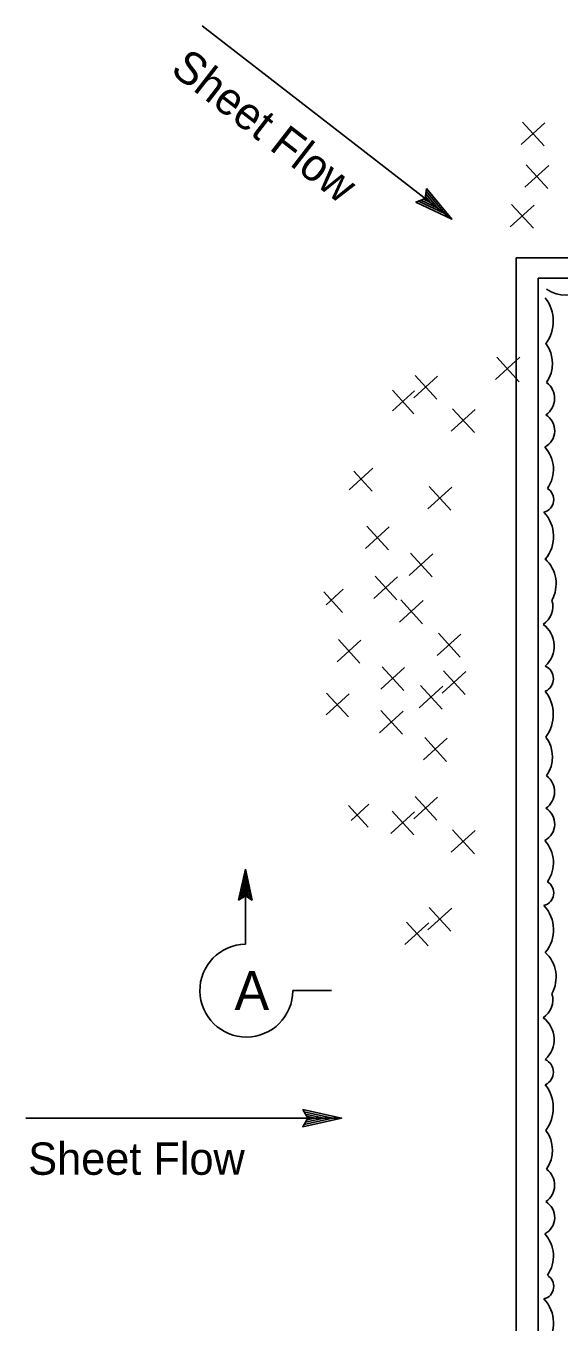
# Model space of a CAD drawing. Extents: x 6708945 to 6710368, y 1871409 to 1872338.
# Drawn here: x 6708945.2 to 6709044.1, y 1871623 to 1871863.4 of the extents above; entities that cross this region are included whole.
import ezdxf

# ---------------------------------------------------------------- set-up
doc = ezdxf.new("R2010")
doc.units = 0
for name, color, linetype in [('1 Control', 7, 'Continuous'), ('57 Undefined', 7, 'Continuous'), ('62 As-Built Chng', 7, 'Continuous'), ('63 Undefined', 7, 'Continuous')]:
    doc.layers.add(name, color=color, linetype=linetype)

msp = doc.modelspace()

# ---------------------------------------------------------------- linework, layer by layer
at = {"layer": '1 Control'}
for p, q in [((6709019.5, 1871833.29), (6709019.5, 1871833.29)), ((6709017.54, 1871830.76), (6709017.54, 1871830.76)), ((6709024.21, 1871827.61), (6709024.21, 1871827.61))]:
    msp.add_line(p, q, dxfattribs=at)
msp.add_lwpolyline([(6709019.5, 1871833.29), (6709024.21, 1871827.61), (6709017.54, 1871830.76), (6709018, 1871830.94), (6709022.89, 1871828.63), (6709019.44, 1871832.8), (6709019.38, 1871832.31), (6709021.59, 1871829.65), (6709018.47, 1871831.12), (6709018.93, 1871831.3), (6709020.28, 1871830.66), (6709019.32, 1871831.82), (6709019.28, 1871831.43), (6709017.54, 1871830.76), (6709019.28, 1871831.43)], close=True, dxfattribs=at)
at = {"layer": '57 Undefined'}
for p, q in [((6709024.21, 1871827.61), (6708977.92, 1871863.44)), ((6709003.78, 1871660.82), (6708945.25, 1871660.82))]:
    msp.add_line(p, q, dxfattribs=at)
at = {"layer": '62 As-Built Chng'}
for p, q in [((6709037.06, 1871841.44), (6709041.46, 1871845.46)), ((6709037.31, 1871845.59), (6709041.33, 1871841.19)), ((6709037.76, 1871833.54), (6709042.16, 1871837.56)), ((6709038.01, 1871837.68), (6709042.03, 1871833.28)), ((6709035.05, 1871826.18), (6709039.45, 1871830.2)), ((6709035.3, 1871830.33), (6709039.32, 1871825.93)), ((6709032.29, 1871797.82), (6709036.82, 1871801.97)), ((6709032.54, 1871801.97), (6709036.72, 1871797.39)), ((6709017.15, 1871794.45), (6709021.55, 1871798.47)), ((6709017.4, 1871798.6), (6709021.42, 1871794.2)), ((6709013.19, 1871795.84), (6709017.16, 1871791.49)), ((6709013.22, 1871792.04), (6709017.29, 1871795.76)), ((6709024.11, 1871788.26), (6709028.51, 1871792.28)), ((6709024.36, 1871792.4), (6709028.38, 1871788.01)), ((6709005.15, 1871777.38), (6709009.55, 1871781.4)), ((6709006.04, 1871780.83), (6709009.42, 1871777.13)), ((6709019.78, 1871773.86), (6709024.18, 1871777.88)), ((6709020.03, 1871778), (6709024.05, 1871773.6)), ((6709008.18, 1871766.51), (6709012.58, 1871770.53)), ((6709008.43, 1871770.65), (6709012.45, 1871766.25)), ((6709016.3, 1871761.48), (6709020.7, 1871765.5)), ((6709016.55, 1871765.62), (6709020.57, 1871761.22)), ((6709009.72, 1871757.22), (6709014.12, 1871761.24)), ((6709009.97, 1871761.37), (6709013.99, 1871756.97)), ((6709000.48, 1871758.43), (6709003.94, 1871754.64)), ((6709000.93, 1871756.05), (6709004.07, 1871758.92)), ((6709014.52, 1871752.8), (6709018.91, 1871756.82)), ((6709014.77, 1871756.94), (6709018.79, 1871752.54)), ((6709021.48, 1871746.61), (6709025.88, 1871750.62)), ((6709021.73, 1871750.75), (6709025.75, 1871746.35)), ((6709002.92, 1871745.45), (6709007.31, 1871749.46)), ((6709003.17, 1871749.59), (6709007.18, 1871745.19)), ((6709011.04, 1871740.41), (6709015.43, 1871744.43)), ((6709011.29, 1871744.56), (6709015.31, 1871740.16)), ((6709022.41, 1871739.63), (6709026.81, 1871743.65)), ((6709022.66, 1871743.78), (6709026.68, 1871739.38)), ((6709018.16, 1871736.92), (6709022.55, 1871740.94)), ((6709018.41, 1871741.07), (6709022.43, 1871736.67)), ((6709000.92, 1871735.65), (6709005.15, 1871739.52)), ((6709001, 1871739.65), (6709005.02, 1871735.25)), ((6709010.81, 1871732.28), (6709015.21, 1871736.3)), ((6709011.06, 1871736.43), (6709015.08, 1871732.03)), ((6709018.93, 1871727.25), (6709023.33, 1871731.27)), ((6709019.18, 1871731.4), (6709023.2, 1871727)), ((6709005.53, 1871716.04), (6709008.81, 1871719.04)), ((6709017.15, 1871716.31), (6709021.55, 1871720.33)), ((6709017.4, 1871720.46), (6709021.42, 1871716.06)), ((6709005.02, 1871718.78), (6709008.69, 1871714.77)), ((6709012.89, 1871713.61), (6709017.29, 1871717.62)), ((6709013.14, 1871717.75), (6709017.16, 1871713.35)), ((6709024.11, 1871710.12), (6709028.51, 1871714.14)), ((6709024.36, 1871714.27), (6709028.38, 1871709.87)), ((6708984.65, 1871701.25), (6708985.94, 1871707.02)), ((6708985.94, 1871707.02), (6708985.94, 1871707.02)), ((6708985.94, 1871707.02), (6708987.22, 1871701.25)), ((6708985.94, 1871707.02), (6708985.94, 1871693.08)), ((6708985, 1871701.46), (6708985.94, 1871705.69)), ((6708985.94, 1871705.68), (6708986.87, 1871701.48)), ((6708985.94, 1871702.02), (6708984.65, 1871701.25)), ((6708985.34, 1871701.69), (6708985.94, 1871704.36)), ((6708985.67, 1871701.85), (6708985.94, 1871703.03)), ((6708985.94, 1871704.36), (6708986.54, 1871701.65)), ((6708985.94, 1871703.03), (6708986.2, 1871701.87)), ((6708987.22, 1871701.25), (6708985.94, 1871702.02)), ((6708984.65, 1871701.25), (6708984.65, 1871701.25)), ((6708987.22, 1871701.25), (6708987.22, 1871701.25)), ((6709019.78, 1871695.72), (6709024.18, 1871699.74)), ((6709020.03, 1871699.87), (6709024.05, 1871695.47)), ((6709015.52, 1871693.01), (6709019.92, 1871697.03)), ((6709015.78, 1871697.16), (6709019.79, 1871692.76)), ((6708994.74, 1871684.46), (6709001.87, 1871684.46)), ((6708996.58, 1871662.43), (6708996.58, 1871662.43)), ((6708996.58, 1871659.22), (6708996.58, 1871659.22)), ((6709003.78, 1871660.82), (6709003.78, 1871660.82))]:
    msp.add_line(p, q, dxfattribs=at)
for points in [[(6709036.13, 1871820.42), (6709330.46, 1871820.42), (6709330.46, 1871528.03), (6709036.13, 1871528.03)], [(6709040.24, 1871816.63), (6709326.68, 1871816.63), (6709326.68, 1871531.81), (6709040.24, 1871531.81)], [(6708996.58, 1871662.43), (6709003.78, 1871660.82), (6708996.58, 1871659.22), (6708996.84, 1871659.65), (6709002.11, 1871660.81), (6708996.84, 1871662), (6708997.09, 1871661.57), (6709000.47, 1871660.82), (6708997.1, 1871660.07), (6708997.35, 1871660.5), (6708998.81, 1871660.82), (6708997.35, 1871661.15), (6708997.54, 1871660.82), (6708996.58, 1871659.22), (6708997.54, 1871660.82)]]:
    msp.add_lwpolyline(points, close=True, dxfattribs=at)
msp.add_arc((6708986.11, 1871684.47), 8.62, 91.113, 359.9585, dxfattribs=at)
at = {"layer": '63 Undefined'}
for centre, radius, start, end in [((6709036.01, 1871808.66), 7, 323.3979, 37.9353), ((6709045.28, 1871819.69), 6.2, 235.656, 306.6973), ((6709036.67, 1871800.79), 6.2, 325.656, 36.6973), ((6709039.59, 1871794.34), 3.68, 303.6905, 53.3403), ((6709039.88, 1871788.35), 3.41, 297.0211, 59.1913), ((6709036.95, 1871781.17), 6.1, 324.5002, 42.8354), ((6709040.7, 1871775.56), 2.4, 284.0578, 59.3233), ((6709036.53, 1871768.74), 6.54, 319.9986, 43.3536), ((6709037.18, 1871759.9), 6.36, 331.3634, 46.8458), ((6709039.06, 1871755.69), 3.88, 302.3474, 17.3796), ((6709038.18, 1871748.38), 5, 312.1292, 53.705), ((6709040.47, 1871742.33), 2.57, 294.5196, 65.4804), ((6709036.01, 1871735.68), 7, 323.3979, 37.9353), ((6709036.67, 1871727.8), 6.2, 325.656, 36.6973), ((6709039.59, 1871721.36), 3.68, 303.6905, 53.3403), ((6709039.88, 1871715.37), 3.41, 297.0211, 59.1913), ((6709036.95, 1871708.18), 6.1, 324.5002, 42.8354), ((6709040.7, 1871702.58), 2.4, 284.0578, 59.3233), ((6709036.53, 1871695.76), 6.54, 319.9986, 43.3536), ((6709037.18, 1871686.92), 6.36, 331.3634, 46.8458), ((6709039.06, 1871682.71), 3.88, 302.3474, 17.3796), ((6709038.18, 1871675.4), 5, 312.1292, 53.705), ((6709040.47, 1871669.34), 2.57, 294.5196, 65.4804), ((6709036.01, 1871662.7), 7, 323.3979, 37.9353), ((6709036.67, 1871654.82), 6.2, 325.656, 36.6973), ((6709039.59, 1871648.37), 3.68, 303.6905, 53.3403), ((6709039.88, 1871642.38), 3.41, 297.0211, 59.1913), ((6709036.95, 1871635.2), 6.1, 324.5002, 42.8354), ((6709040.7, 1871629.59), 2.4, 284.0578, 59.3233), ((6709036.53, 1871622.78), 6.54, 319.9986, 43.3536)]:
    msp.add_arc(centre, radius, start, end, dxfattribs=at)

# ---------------------------------------------------------------- texts
at = {"layer": '57 Undefined'}
msp.add_text('Sheet Flow', height=6, rotation=322.2639, dxfattribs=at).set_placement((6708971.81, 1871854.85))
msp.add_text('Sheet Flow', height=6, dxfattribs=at).set_placement((6708945.68, 1871650.29))
at = {"layer": '62 As-Built Chng'}
msp.add_text('A', height=7.21, dxfattribs=at).set_placement((6708983.91, 1871680.87))

doc.saveas('drawing.dxf')
